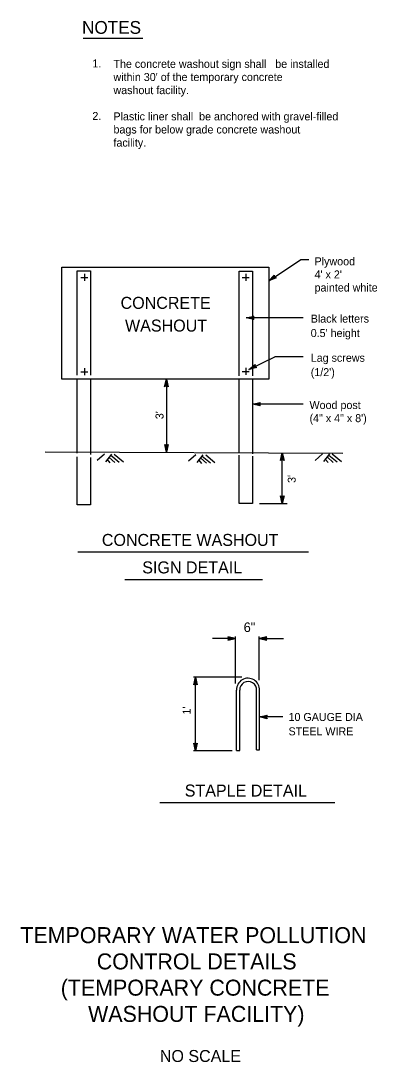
# Model space of a CAD drawing. Extents: x 6708826 to 6711089, y 1868571 to 1869537.
# Drawn here: x 6709948 to 6710215, y 1868584 to 1869365 of the extents above; entities that cross this region are included whole.
import ezdxf

# ---------------------------------------------------------------- set-up
doc = ezdxf.new("R2010")
doc.units = 0
for name, color, linetype in [('10 Sheet Formats', 7, 'Continuous'), ('56 Stg 3 Anno', 7, 'Continuous'), ('57 Undefined', 7, 'Continuous'), ('59 Soundwall Ann', 7, 'Continuous'), ('60 Nongeo Data', 7, 'Continuous')]:
    doc.layers.add(name, color=color, linetype=linetype)

msp = doc.modelspace()

# ---------------------------------------------------------------- linework, layer by layer
at = {"layer": '56 Stg 3 Anno'}
for p, q in [((6710133.73, 1869170.39), (6710157.57, 1869186.15)), ((6710163.81, 1869186.15), (6710157.57, 1869186.15)), ((6710133.73, 1869170.39), (6710137.84, 1869174.63)), ((6710139.25, 1869172.5), (6710133.73, 1869170.39)), ((6710133.73, 1869170.39), (6710133.73, 1869170.39)), ((6710138.89, 1869172.67), (6710134.84, 1869171.12)), ((6710134.85, 1869171.13), (6710137.84, 1869174.22)), ((6710135.95, 1869171.85), (6710137.88, 1869173.85)), ((6710138.51, 1869172.83), (6710135.95, 1869171.85)), ((6710137.05, 1869172.58), (6710137.88, 1869173.44)), ((6710138.18, 1869173.01), (6710137.05, 1869172.58)), ((6710137.84, 1869174.63), (6710137.84, 1869174.63)), ((6710137.84, 1869174.63), (6710137.9, 1869173.15)), ((6710137.9, 1869173.15), (6710139.25, 1869172.5)), ((6710139.25, 1869172.5), (6710139.25, 1869172.5)), ((6710116.73, 1869142.56), (6710122.49, 1869143.84)), ((6710159.65, 1869142.56), (6710116.73, 1869142.56)), ((6710122.49, 1869141.28), (6710116.73, 1869142.56)), ((6710116.73, 1869142.56), (6710116.73, 1869142.56)), ((6710122.28, 1869141.62), (6710118.05, 1869142.56)), ((6710118.06, 1869142.57), (6710122.26, 1869143.49)), ((6710119.38, 1869142.56), (6710122.09, 1869143.16)), ((6710122.06, 1869141.96), (6710119.38, 1869142.56)), ((6710120.71, 1869142.56), (6710121.87, 1869142.82)), ((6710121.89, 1869142.3), (6710120.71, 1869142.56)), ((6710122.49, 1869143.84), (6710121.72, 1869142.56)), ((6710121.72, 1869142.56), (6710122.49, 1869141.28)), ((6710122.49, 1869143.84), (6710122.49, 1869143.84)), ((6710122.49, 1869141.28), (6710122.49, 1869141.28)), ((6710118.81, 1869103.85), (6710138.25, 1869113.25)), ((6710159.65, 1869113.22), (6710138.26, 1869113.22)), ((6710118.81, 1869103.85), (6710123.44, 1869107.5)), ((6710124.55, 1869105.2), (6710118.81, 1869103.85)), ((6710124.22, 1869105.41), (6710120, 1869104.42)), ((6710120.01, 1869104.43), (6710123.38, 1869107.1)), ((6710121.2, 1869105), (6710123.38, 1869106.72)), ((6710123.87, 1869105.63), (6710121.2, 1869105)), ((6710122.39, 1869105.58), (6710123.32, 1869106.31)), ((6710123.57, 1869105.85), (6710122.39, 1869105.58)), ((6710123.44, 1869107.5), (6710123.3, 1869106.02)), ((6710123.3, 1869106.02), (6710124.55, 1869105.2)), ((6710123.44, 1869107.5), (6710123.44, 1869107.5)), ((6710124.55, 1869105.2), (6710124.55, 1869105.2)), ((6710118.81, 1869103.85), (6710118.81, 1869103.85)), ((6710055.69, 1869090.93), (6710056.98, 1869096.69)), ((6710056.98, 1869091.7), (6710055.69, 1869090.93)), ((6710055.69, 1869090.93), (6710055.69, 1869090.93)), ((6710056.04, 1869091.14), (6710056.98, 1869095.37)), ((6710056.38, 1869091.36), (6710056.98, 1869094.04)), ((6710056.71, 1869091.53), (6710056.98, 1869092.71)), ((6710056.98, 1869096.69), (6710056.98, 1869041.71)), ((6710056.98, 1869096.69), (6710056.98, 1869096.69)), ((6710056.98, 1869096.69), (6710058.26, 1869090.93)), ((6710056.98, 1869095.36), (6710057.91, 1869091.16)), ((6710056.98, 1869094.04), (6710057.58, 1869091.33)), ((6710056.98, 1869092.71), (6710057.23, 1869091.55)), ((6710058.26, 1869090.93), (6710056.98, 1869091.7)), ((6710058.26, 1869090.93), (6710058.26, 1869090.93)), ((6710121.49, 1869077.77), (6710127.25, 1869079.05)), ((6710159.65, 1869077.77), (6710121.49, 1869077.77)), ((6710127.25, 1869076.49), (6710121.49, 1869077.77)), ((6710121.49, 1869077.77), (6710121.49, 1869077.77)), ((6710127.05, 1869076.83), (6710122.82, 1869077.77)), ((6710122.83, 1869077.78), (6710127.03, 1869078.7)), ((6710124.15, 1869077.77), (6710126.86, 1869078.37)), ((6710126.82, 1869077.17), (6710124.15, 1869077.77)), ((6710125.47, 1869077.77), (6710126.63, 1869078.03)), ((6710126.65, 1869077.51), (6710125.47, 1869077.77)), ((6710127.25, 1869079.05), (6710126.49, 1869077.77)), ((6710126.49, 1869077.77), (6710127.25, 1869076.49)), ((6710127.25, 1869079.05), (6710127.25, 1869079.05)), ((6710127.25, 1869076.49), (6710127.25, 1869076.49)), ((6710056.98, 1869041.71), (6710055.7, 1869047.47)), ((6710055.7, 1869047.47), (6710055.7, 1869047.47)), ((6710055.7, 1869047.47), (6710056.98, 1869046.7)), ((6710056.98, 1869043.05), (6710056.05, 1869047.25)), ((6710056.98, 1869044.36), (6710056.38, 1869047.08)), ((6710056.98, 1869045.69), (6710056.73, 1869046.85)), ((6710056.98, 1869046.7), (6710058.27, 1869047.47)), ((6710058.27, 1869047.47), (6710056.98, 1869041.71)), ((6710057.92, 1869047.26), (6710056.98, 1869043.04)), ((6710057.58, 1869047.04), (6710056.98, 1869044.36)), ((6710057.25, 1869046.87), (6710056.98, 1869045.69)), ((6710058.27, 1869047.47), (6710058.27, 1869047.47)), ((6710056.98, 1869041.71), (6710056.98, 1869041.71)), ((6710142.62, 1869035.55), (6710143.91, 1869041.31)), ((6710143.91, 1869036.32), (6710142.62, 1869035.55)), ((6710142.62, 1869035.55), (6710142.62, 1869035.55)), ((6710142.97, 1869035.76), (6710143.91, 1869039.99)), ((6710143.31, 1869035.98), (6710143.91, 1869038.66)), ((6710143.64, 1869036.15), (6710143.91, 1869037.33)), ((6710143.91, 1869003.4), (6710143.91, 1869041.31)), ((6710143.91, 1869041.31), (6710143.91, 1869041.31)), ((6710143.91, 1869041.31), (6710145.19, 1869035.55)), ((6710143.91, 1869039.97), (6710144.84, 1869035.78)), ((6710143.91, 1869038.66), (6710144.51, 1869035.95)), ((6710143.91, 1869037.33), (6710144.17, 1869036.17)), ((6710145.19, 1869035.55), (6710143.91, 1869036.32)), ((6710145.19, 1869035.55), (6710145.19, 1869035.55)), ((6710143.91, 1869003.4), (6710142.63, 1869009.16)), ((6710142.63, 1869009.16), (6710142.63, 1869009.16)), ((6710142.63, 1869009.16), (6710143.91, 1869008.39)), ((6710143.91, 1869003.4), (6710142.63, 1869009.16)), ((6710142.63, 1869009.16), (6710142.63, 1869009.16)), ((6710142.63, 1869009.16), (6710143.91, 1869008.39)), ((6710143.91, 1869004.73), (6710142.98, 1869008.93)), ((6710143.91, 1869004.73), (6710142.98, 1869008.93)), ((6710143.91, 1869006.05), (6710143.31, 1869008.76)), ((6710143.91, 1869006.05), (6710143.31, 1869008.76)), ((6710143.91, 1869007.38), (6710143.66, 1869008.54)), ((6710143.91, 1869007.38), (6710143.66, 1869008.54)), ((6710143.91, 1869008.39), (6710145.2, 1869009.16)), ((6710145.2, 1869009.16), (6710143.91, 1869003.4)), ((6710143.91, 1869008.39), (6710145.2, 1869009.16)), ((6710145.2, 1869009.16), (6710143.91, 1869003.4)), ((6710144.86, 1869008.95), (6710143.91, 1869004.72)), ((6710144.86, 1869008.95), (6710143.91, 1869004.72)), ((6710144.51, 1869008.72), (6710143.91, 1869006.05)), ((6710144.51, 1869008.72), (6710143.91, 1869006.05)), ((6710144.18, 1869008.56), (6710143.91, 1869007.38)), ((6710144.18, 1869008.56), (6710143.91, 1869007.38)), ((6710145.2, 1869009.16), (6710145.2, 1869009.16)), ((6710145.2, 1869009.16), (6710145.2, 1869009.16)), ((6710126.68, 1869003.4), (6710147.56, 1869003.4)), ((6710143.91, 1869003.4), (6710143.91, 1869003.4)), ((6710143.91, 1869003.4), (6710143.91, 1869003.4)), ((6710108.82, 1868902.09), (6710103.06, 1868903.37)), ((6710103.06, 1868903.37), (6710103.06, 1868903.37)), ((6710103.06, 1868903.37), (6710103.82, 1868902.09)), ((6710107.48, 1868902.09), (6710103.28, 1868903.02)), ((6710106.16, 1868902.09), (6710103.45, 1868902.69)), ((6710104.84, 1868902.09), (6710103.68, 1868902.34)), ((6710108.82, 1868868.32), (6710108.82, 1868903.53)), ((6710126.53, 1868870.94), (6710126.53, 1868903.53)), ((6710132.3, 1868903.37), (6710126.54, 1868902.09)), ((6710132.09, 1868903.03), (6710127.86, 1868902.09)), ((6710131.87, 1868902.69), (6710129.19, 1868902.09)), ((6710131.7, 1868902.36), (6710130.52, 1868902.09)), ((6710131.53, 1868902.09), (6710132.3, 1868903.37)), ((6710132.3, 1868903.37), (6710132.3, 1868903.37)), ((6710108.74, 1868902.09), (6710091.5, 1868902.09)), ((6710103.82, 1868902.09), (6710103.06, 1868900.8)), ((6710103.06, 1868900.8), (6710108.82, 1868902.09)), ((6710103.06, 1868900.8), (6710103.06, 1868900.8)), ((6710103.26, 1868901.14), (6710107.49, 1868902.09)), ((6710103.49, 1868901.49), (6710106.16, 1868902.09)), ((6710103.66, 1868901.82), (6710104.84, 1868902.09)), ((6710108.82, 1868902.09), (6710108.82, 1868902.09)), ((6710126.54, 1868902.09), (6710126.54, 1868902.09)), ((6710126.54, 1868902.09), (6710132.3, 1868900.81)), ((6710126.97, 1868902.09), (6710144.68, 1868902.09)), ((6710127.87, 1868902.09), (6710132.07, 1868901.16)), ((6710129.19, 1868902.09), (6710131.9, 1868901.49)), ((6710130.52, 1868902.09), (6710131.68, 1868901.83)), ((6710132.3, 1868900.81), (6710131.53, 1868902.09)), ((6710132.3, 1868900.81), (6710132.3, 1868900.81)), ((6710113.47, 1868872.99), (6710077.34, 1868872.99)), ((6710077.5, 1868867.23), (6710078.78, 1868872.99)), ((6710077.84, 1868867.44), (6710078.78, 1868871.67)), ((6710078.78, 1868817.93), (6710078.78, 1868872.99)), ((6710078.78, 1868872.99), (6710078.78, 1868872.99)), ((6710078.78, 1868872.99), (6710080.06, 1868867.23)), ((6710078.79, 1868871.66), (6710079.71, 1868867.46)), ((6710078.78, 1868868), (6710077.5, 1868867.23)), ((6710077.5, 1868867.23), (6710077.5, 1868867.23)), ((6710078.18, 1868867.67), (6710078.78, 1868870.34)), ((6710078.52, 1868867.84), (6710078.78, 1868869.02)), ((6710078.78, 1868870.34), (6710079.38, 1868867.63)), ((6710078.78, 1868869.02), (6710079.04, 1868867.86)), ((6710080.06, 1868867.23), (6710078.78, 1868868)), ((6710080.06, 1868867.23), (6710080.06, 1868867.23)), ((6710126.74, 1868843.26), (6710132.5, 1868844.54)), ((6710144.29, 1868843.26), (6710126.74, 1868843.26)), ((6710132.5, 1868841.97), (6710126.74, 1868843.26)), ((6710126.74, 1868843.26), (6710126.74, 1868843.26)), ((6710132.29, 1868842.32), (6710128.06, 1868843.26)), ((6710128.07, 1868843.26), (6710132.27, 1868844.19)), ((6710129.39, 1868843.26), (6710132.1, 1868843.86)), ((6710132.07, 1868842.66), (6710129.39, 1868843.26)), ((6710130.72, 1868843.26), (6710131.88, 1868843.52)), ((6710131.9, 1868842.99), (6710130.72, 1868843.26)), ((6710132.5, 1868844.54), (6710131.73, 1868843.26)), ((6710131.73, 1868843.26), (6710132.5, 1868841.97)), ((6710132.5, 1868844.54), (6710132.5, 1868844.54)), ((6710132.5, 1868841.97), (6710132.5, 1868841.97)), ((6710106.29, 1868817.93), (6710077.34, 1868817.93)), ((6710078.78, 1868817.93), (6710077.51, 1868823.69)), ((6710077.51, 1868823.69), (6710077.51, 1868823.69)), ((6710077.51, 1868823.69), (6710078.78, 1868822.93)), ((6710078.78, 1868819.27), (6710077.85, 1868823.47)), ((6710078.78, 1868820.59), (6710078.18, 1868823.3)), ((6710078.79, 1868821.91), (6710078.53, 1868823.07)), ((6710078.78, 1868822.93), (6710080.07, 1868823.69)), ((6710080.07, 1868823.69), (6710078.78, 1868817.93)), ((6710079.73, 1868823.49), (6710078.78, 1868819.26)), ((6710079.38, 1868823.26), (6710078.78, 1868820.59)), ((6710078.78, 1868817.93), (6710078.78, 1868817.93)), ((6710079.05, 1868823.09), (6710078.79, 1868821.91)), ((6710080.07, 1868823.69), (6710080.07, 1868823.69))]:
    msp.add_line(p, q, dxfattribs=at)
at = {"layer": '57 Undefined'}
for p, q in [((6709994.69, 1869352.32), (6710039.45, 1869352.32)), ((6709990.51, 1868967.03), (6710163.59, 1868967.03)), ((6710025.88, 1868946.43), (6710129.09, 1868946.43)), ((6710052.16, 1868779.09), (6710183.28, 1868779.09))]:
    msp.add_line(p, q, dxfattribs=at)
at = {"layer": '59 Soundwall Ann'}
for p, q in [((6710010.6, 1869040.37), (6710005.12, 1869035.5)), ((6710015.79, 1869040.33), (6710011.27, 1869034.59)), ((6710012.71, 1869036.24), (6710014.69, 1869033.81)), ((6710014.21, 1869037.89), (6710018.44, 1869034.04)), ((6710015.34, 1869039.47), (6710021.53, 1869034.38)), ((6710017.9, 1869040.31), (6710024.82, 1869034.61)), ((6710079.17, 1869039.84), (6710073.69, 1869034.96)), ((6710084.36, 1869039.8), (6710079.85, 1869034.05)), ((6710081.29, 1869035.7), (6710083.27, 1869033.27)), ((6710082.79, 1869037.35), (6710087.01, 1869033.51)), ((6710083.92, 1869038.94), (6710090.11, 1869033.84)), ((6710086.47, 1869039.78), (6710093.4, 1869034.08)), ((6710174.06, 1869040.52), (6710168.58, 1869035.64)), ((6710179.26, 1869040.48), (6710174.74, 1869034.73)), ((6710176.18, 1869036.38), (6710178.16, 1869033.95)), ((6710177.68, 1869038.03), (6710181.91, 1869034.18)), ((6710178.81, 1869039.62), (6710185, 1869034.52)), ((6710181.37, 1869040.46), (6710188.29, 1869034.76))]:
    msp.add_line(p, q, dxfattribs=at)
at = {"layer": '60 Nongeo Data'}
for p, q in [((6709995.56, 1869175.56), (6709995.56, 1869170.28)), ((6710116.57, 1869175.56), (6710116.57, 1869170.28)), ((6709992.77, 1869172.78), (6709998.06, 1869172.78)), ((6710113.79, 1869172.78), (6710119.08, 1869172.78)), ((6709992.77, 1869101.96), (6709998.06, 1869101.96)), ((6709995.56, 1869104.74), (6709995.56, 1869099.46)), ((6710113.79, 1869102.24), (6710119.08, 1869102.24)), ((6710116.57, 1869105.01), (6710116.57, 1869099.74)), ((6709966.19, 1869042.1), (6710189.37, 1869041.15)), ((6710109.61, 1868818.08), (6710109.61, 1868863.41)), ((6710111.97, 1868818.08), (6710111.97, 1868863.27)), ((6710124.65, 1868818.52), (6710124.65, 1868863.11)), ((6710126.74, 1868818.52), (6710126.74, 1868863.2)), ((6710109.61, 1868818.08), (6710111.97, 1868818.08)), ((6710124.65, 1868818.52), (6710126.74, 1868818.52))]:
    msp.add_line(p, q, dxfattribs=at)
msp.add_lwpolyline([(6709978.52, 1869180.56), (6710133.73, 1869180.56), (6710133.73, 1869096.69), (6709978.52, 1869096.69)], close=True, dxfattribs=at)
for points in [[(6709990.2, 1869099.47), (6709990.2, 1869177.78), (6710000.22, 1869177.78), (6710000.22, 1869099.47)], [(6710111.48, 1869099.19), (6710111.48, 1869177.5), (6710121.49, 1869177.5), (6710121.49, 1869099.19)], [(6709990.2, 1869041.15), (6709990.2, 1869096.13)], [(6710000.22, 1869096.13), (6710000.22, 1869040.04)], [(6710111.48, 1869041.71), (6710111.48, 1869096.69)], [(6710121.49, 1869096.69), (6710121.49, 1869040.6)], [(6710000.22, 1869037.82), (6710000.22, 1869002.27), (6709990.2, 1869002.27), (6709990.2, 1869038.37)], [(6710121.49, 1869038.93), (6710121.49, 1869003.38), (6710111.48, 1869003.38), (6710111.48, 1869039.48)]]:
    msp.add_lwpolyline(points, dxfattribs=at)
for centre, major_axis in [((6710118.18, 1868863.72), (0, -8.58)), ((6710118.31, 1868863.5), (0, -6.35))]:
    msp.add_ellipse(centre, major_axis=major_axis, ratio=0.999991, start_param=1.510257, end_param=4.748244, dxfattribs=at)

# ---------------------------------------------------------------- texts
at = {"layer": '10 Sheet Formats'}
for s, height, p in [('TEMPORARY WATER POLLUTION', 12, (6709947.5, 1868673.63)), ('CONTROL DETAILS', 12, (6710004.8, 1868653.95)), ('(TEMPORARY CONCRETE', 12, (6709977.78, 1868634.27)), ('WASHOUT FACILITY)', 12, (6709998.29, 1868614.59)), ('NO SCALE', 9, (6710052.09, 1868584.51))]:
    msp.add_text(s, height=height, dxfattribs=at).set_placement(p)
at = {"layer": '57 Undefined'}
for s, height, p in [('NOTES', 9.6, (6709993.76, 1869355.54)), ('1.', 6, (6710001.5, 1869330.32)), ('The concrete washout sign shall   be installed ', 6, (6710017.31, 1869329.99)), ("within 30' of the temporary concrete ", 6, (6710017.31, 1869320.15)), ('washout facility.', 6, (6710017.31, 1869310.31)), ('2.', 6, (6710001.5, 1869290.96)), ('Plastic liner shall  be anchored with gravel-filled ', 6, (6710017.31, 1869290.63)), ('bags for below grade concrete washout ', 6, (6710017.31, 1869280.79)), ('facility.', 6, (6710017.31, 1869270.95)), ('Plywood', 6, (6710168.09, 1869181.95)), ("4' x 2'", 6, (6710168.09, 1869172.11)), ('painted white', 6, (6710168.09, 1869162.27)), ('Black letters', 6, (6710165.2, 1869138.96)), ("0.5' height", 6, (6710165.2, 1869128.16)), ('Lag screws', 6, (6710165.23, 1869109.62)), ("(1/2')", 6, (6710165.23, 1869098.82)), ('Wood post', 6, (6710164.31, 1869074.17)), ('(4" x 4" x 8\')', 6, (6710164.31, 1869064.33)), ('CONCRETE WASHOUT', 9, (6710008.62, 1868971.51)), ('SIGN DETAIL', 9, (6710038.89, 1868950.91)), ('6" ', 7.2, (6710114.91, 1868906.94)), ('10 GAUGE DIA', 6, (6710148.57, 1868840.25)), ('STEEL WIRE', 6, (6710148.57, 1868829.45)), ('STAPLE DETAIL', 9, (6710070.74, 1868783.57))]:
    msp.add_text(s, height=height, dxfattribs=at).set_placement(p)
for s, p in [("3'", (6710054.84, 1869066.53)), ("3'", (6710153.95, 1869018.75)), ("1' ", (6710075.21, 1868845.08))]:
    msp.add_text(s, height=6, rotation=90, dxfattribs=at).set_placement(p)
at = {"layer": '60 Nongeo Data'}
for s, p in [('CONCRETE', (6710022.66, 1869149.29)), ('WASHOUT', (6710025.98, 1869132.24))]:
    msp.add_text(s, height=9, dxfattribs=at).set_placement(p)

doc.saveas('drawing.dxf')
